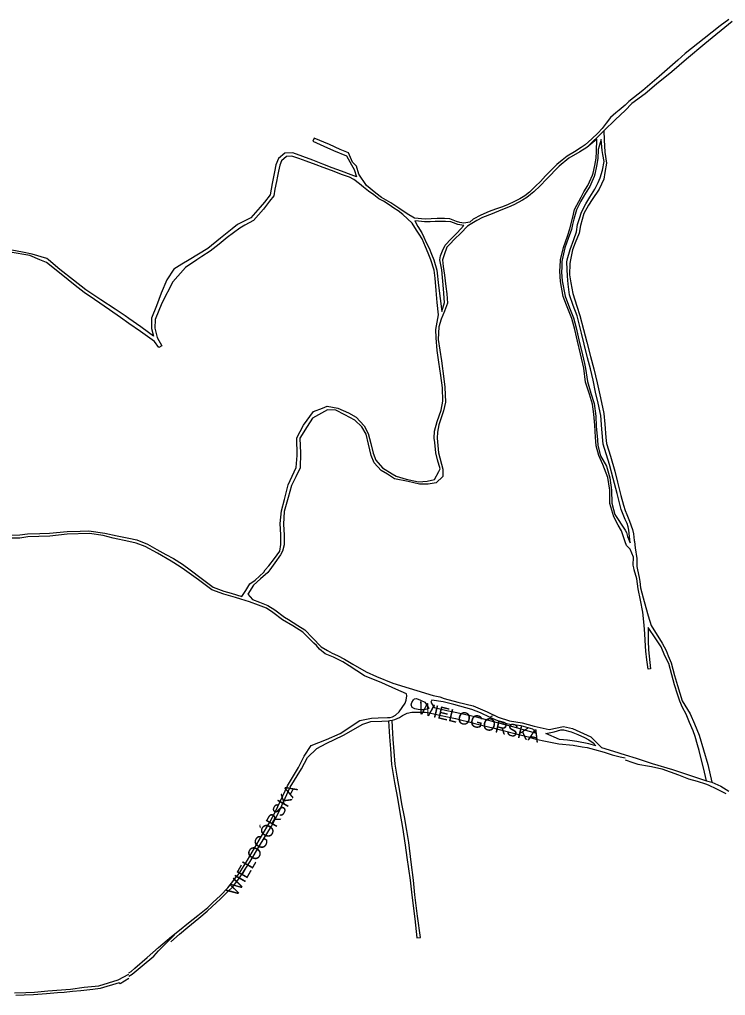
# Model space of a CAD drawing. Extents: x -304109 to -273954, y 21500 to 39796.
# Drawn here: x -301688 to -301119, y 25157 to 25944 of the extents above; entities that cross this region are included whole.
import ezdxf

# ---------------------------------------------------------------- set-up
doc = ezdxf.new("R2010")
doc.units = 0
doc.layers.add('krawedzie_ulic', color=7, linetype='Continuous')
doc.layers.add('nazwy_ulic', color=7, linetype='Continuous')

msp = doc.modelspace()

# ---------------------------------------------------------------- linework, layer by layer
at = {"layer": 'krawedzie_ulic'}
for points in [[(-301116.309, 25943.567), (-301123.262, 25938.471), (-301136.315, 25928.304), (-301151.605, 25916.218), (-301157.425, 25910.905), (-301172.587, 25897.713), (-301185.766, 25886.389), (-301196.913, 25877.455), (-301200, 25874.543), (-301204.865, 25870.477), (-301207.397, 25868.469), (-301211.799, 25864.543), (-301215.12, 25860.156), (-301218.467, 25855.732), (-301221.889, 25851.969), (-301226.826, 25847.343), (-301232.042, 25842.616), (-301235.374, 25840.52), (-301240.831, 25836.9), (-301246.581, 25833.421), (-301250.601, 25830.194)], [(-301113.534, 25942.068), (-301135.789, 25923.881), (-301150.392, 25911.718), (-301162.351, 25901.513), (-301174.705, 25891.397), (-301183.678, 25883.771), (-301194.583, 25875.803), (-301200, 25870.19), (-301207.642, 25863.035), (-301217.031, 25853.782)], [(-301217.031, 25853.782), (-301216.782, 25846.515), (-301216.406, 25836.663), (-301214.861, 25827.904), (-301216.264, 25820.282), (-301217.234, 25814.976), (-301220.926, 25806.874), (-301226.615, 25798.469), (-301229.441, 25794.044), (-301233.272, 25787.304), (-301236.025, 25777.634), (-301237.033, 25771.476), (-301240.255, 25763.665), (-301242.395, 25758.056), (-301243.976, 25750), (-301244.619, 25746.863), (-301244.717, 25737.712), (-301243.844, 25731.326), (-301242.125, 25722.714), (-301238.748, 25712.554), (-301236.447, 25705.153), (-301233.421, 25693.656), (-301230.832, 25683.571), (-301227.781, 25672.125), (-301225.269, 25661.988), (-301222.511, 25650.719), (-301219.699, 25638.624), (-301217.191, 25626.018), (-301216.35, 25617.443), (-301215.49, 25606.869), (-301214.94, 25602.06), (-301211.727, 25591.62), (-301208.152, 25579.526), (-301205.987, 25570.763), (-301203.409, 25560.079), (-301201.324, 25552.232), (-301200, 25547.845), (-301198.445, 25544.823), (-301196.379, 25539.329), (-301194.044, 25532.727), (-301193.316, 25529.192), (-301192.699, 25523.837), (-301192.393, 25522.959), (-301191.803, 25517.808), (-301190.42, 25509.363), (-301190.591, 25502.812), (-301189.921, 25500), (-301188.586, 25493.897), (-301188.14, 25490.607), (-301187.496, 25485.562), (-301185.262, 25477.485), (-301183.144, 25469.827), (-301181.271, 25463.071), (-301178.834, 25455.185), (-301170.151, 25441.09), (-301166.932, 25435.024), (-301165.109, 25430.899), (-301162.744, 25425.136), (-301160.158, 25414.975), (-301157.745, 25406.835), (-301153.916, 25394.594), (-301147.524, 25383.974), (-301144.082, 25376.079), (-301140.367, 25366.862), (-301136.82, 25355.078), (-301133.286, 25343.344), (-301130.021, 25328.915)], [(-301217.031, 25853.782), (-301230.81, 25840.552)], [(-301277.089, 25804.47), (-301280.893, 25801.484), (-301284.811, 25799.071), (-301289.618, 25796.57), (-301294.299, 25794.541), (-301298.903, 25792.765), (-301304.409, 25790.762), (-301309.636, 25788.822), (-301316.276, 25785.827), (-301322.342, 25782.666), (-301325.256, 25780.239), (-301330.037, 25779.431), (-301333.203, 25780.072), (-301335.859, 25780.89), (-301341.16, 25782.883), (-301345.61, 25783.36), (-301351.599, 25783.127), (-301361.186, 25782.809), (-301369.654, 25783.622), (-301375.577, 25786.965), (-301382.478, 25791.608), (-301388.833, 25795.944), (-301396.472, 25800.154), (-301400.945, 25803.762), (-301408.443, 25809.92), (-301414.655, 25818.927), (-301416.532, 25825.433), (-301419.633, 25828.594), (-301423.035, 25836.133), (-301429.722, 25838.917), (-301438.429, 25842.811), (-301450.772, 25847.995), (-301451.841, 25845.553), (-301442.803, 25841.633), (-301435.113, 25838.097), (-301424.563, 25833.654), (-301420.664, 25826.457), (-301418.339, 25822.814), (-301416.474, 25816.715), (-301420.91, 25818.516), (-301428.499, 25821.441), (-301436.216, 25824.188), (-301443.728, 25827.125), (-301451.724, 25830.127), (-301459.834, 25833.231), (-301467.779, 25836.17), (-301474.225, 25835.771), (-301479.403, 25831.604), (-301481.504, 25826.579), (-301482.678, 25820.764), (-301484.464, 25811.438), (-301486.25, 25802.302), (-301490.843, 25796.339), (-301494.241, 25792.245), (-301501.748, 25783.805), (-301512.457, 25778.486), (-301516.897, 25774.814), (-301526.222, 25767.471), (-301536.501, 25759.11), (-301551.573, 25750), (-301557.458, 25746.379), (-301563.92, 25742.379), (-301569.528, 25733.787), (-301573.933, 25723.06), (-301577.781, 25712.92), (-301581.832, 25702.831), (-301581.755, 25694.61), (-301580.285, 25688.39), (-301584.136, 25691.409), (-301590.307, 25695.848), (-301600, 25702.587), (-301603.048, 25704.798), (-301611.02, 25710.267), (-301622.593, 25717.817), (-301634.805, 25725.733), (-301644.751, 25733.635), (-301655.757, 25742.155), (-301664.907, 25750), (-301666.282, 25750.894), (-301678.113, 25754.592), (-301685.81, 25755.996), (-301694.308, 25757.669)], [(-301134.314, 25330.224), (-301136.646, 25340.525), (-301138.831, 25349.035), (-301140.355, 25354.495), (-301141.518, 25359.017), (-301143.417, 25365.9), (-301145.166, 25370.42), (-301148.031, 25377.211), (-301150.781, 25383.876), (-301153.64, 25389.32), (-301155.938, 25394.334), (-301157.73, 25400.035), (-301160.063, 25407.349), (-301162.157, 25415.427), (-301164.664, 25424.774), (-301167.882, 25430.814), (-301170.978, 25438.114), (-301175.279, 25444.608), (-301181.27, 25453.539), (-301181.303, 25442.925), (-301181.184, 25435.655), (-301179.378, 25420.243), (-301181.477, 25420.186), (-301182.499, 25427.504), (-301183.24, 25434.493), (-301183.512, 25438.61), (-301184.036, 25448.561), (-301184.587, 25455.626), (-301185.66, 25466.134), (-301187.595, 25475.597), (-301189.402, 25484.87), (-301190.566, 25492.773), (-301192.631, 25500), (-301192.866, 25501.808), (-301193.542, 25503.881), (-301193.219, 25510.317), (-301195.756, 25516.803), (-301198.964, 25519.742), (-301200.034, 25522.596), (-301202.733, 25531.497), (-301205.483, 25536.212), (-301209.18, 25542.757), (-301212.394, 25553.541), (-301212.365, 25564.282), (-301213.975, 25574.459), (-301217.913, 25584.91), (-301221.205, 25592.232), (-301223.265, 25600.054), (-301223.771, 25607.128), (-301224.412, 25616.659), (-301225.255, 25625.654), (-301226.209, 25633.733), (-301228.74, 25641.579), (-301231.811, 25651.434), (-301233.221, 25662.541), (-301236.031, 25674.255), (-301238.212, 25684.29), (-301240.558, 25693.715), (-301242.926, 25702.579), (-301247.133, 25713.462), (-301249.992, 25720.391), (-301252.116, 25732.501), (-301252.537, 25740.874), (-301252.068, 25749.16), (-301251.974, 25750), (-301249.59, 25759.898), (-301246.469, 25769.109), (-301244.444, 25774.782), (-301242.009, 25784.388), (-301240.67, 25790.419), (-301235.413, 25800.314), (-301233.109, 25804.638), (-301230.079, 25809.763), (-301228.641, 25812.676), (-301226.247, 25818.082), (-301225.648, 25819.799), (-301224.36, 25825.996), (-301223.199, 25831.963), (-301223.069, 25837.334), (-301222.808, 25847.121), (-301230.81, 25840.552)], [(-301246.583, 25750), (-301244.225, 25758.224), (-301241.232, 25766.39), (-301239.156, 25772.382), (-301238.377, 25778.312), (-301236.81, 25783.185), (-301235.242, 25788.312), (-301231.741, 25795.142), (-301228.407, 25800.47), (-301224.359, 25806.917), (-301221.686, 25812.17), (-301219.967, 25815.909), (-301218.31, 25822.182), (-301216.907, 25829.04), (-301217.933, 25834.845), (-301218.376, 25837.938), (-301219.21, 25846.925), (-301221.682, 25838.936), (-301221.941, 25831.643), (-301223.127, 25825.357), (-301224.301, 25819.072), (-301224.963, 25816.985), (-301227.497, 25810.829), (-301228.516, 25808.972), (-301231.774, 25803.554), (-301235.669, 25797.183), (-301239.259, 25790.252), (-301241.273, 25782.707), (-301242.242, 25778.407), (-301243.109, 25774.271), (-301245.809, 25767.122), (-301248.484, 25759.528), (-301250.652, 25750), (-301250.921, 25748.59), (-301250.995, 25744.034), (-301251.136, 25740.101), (-301250.731, 25732.963), (-301248.403, 25720.662), (-301244.671, 25711.356), (-301241.529, 25703.168), (-301239.532, 25695.232), (-301237.263, 25685.565), (-301234.286, 25673.496), (-301232.686, 25666.5), (-301231.846, 25662.417), (-301230.401, 25651.909), (-301227.496, 25642.409), (-301225.015, 25634.118), (-301223.647, 25623.915), (-301223.163, 25615.924), (-301222.339, 25604.828), (-301222.045, 25600.324), (-301219.665, 25591.88), (-301215.085, 25583.619), (-301212.333, 25574.234), (-301211.055, 25564.4), (-301210.589, 25553.774), (-301208.168, 25544.656), (-301200.039, 25532.166), (-301198.925, 25530.324), (-301198.056, 25526.953), (-301195.902, 25521.789), (-301196.93, 25531.964), (-301197.556, 25534.686), (-301198.233, 25537.51), (-301200, 25540.807), (-301203.017, 25548.881), (-301206.455, 25561.688), (-301209.648, 25573.821), (-301212.533, 25585.064), (-301217.672, 25601.277), (-301218.614, 25613.466), (-301219.578, 25624.612), (-301221.619, 25634.305), (-301223.708, 25643.233), (-301225.723, 25652.913), (-301227.8, 25662.058), (-301230.182, 25670.961), (-301232.875, 25682.013), (-301235.155, 25690.852), (-301238.506, 25704.703), (-301241.815, 25713.259), (-301244.742, 25721.6), (-301245.813, 25730.315), (-301246.456, 25736.677), (-301246.899, 25747.964), (-301246.583, 25750)], [(-301230.81, 25840.552), (-301236.457, 25837.034), (-301245.425, 25831.867), (-301253.223, 25825.386), (-301263.287, 25814.989), (-301268.516, 25809.536), (-301273.415, 25804.757), (-301276.124, 25802.496), (-301279.292, 25800.056), (-301282.726, 25797.986), (-301286.186, 25796.069), (-301289.645, 25794.305), (-301294.084, 25792.237), (-301300.023, 25790.005), (-301307.209, 25786.935), (-301314.814, 25783.992), (-301319.622, 25781.542), (-301324.875, 25778.431), (-301327.038, 25776.945), (-301332.471, 25771.378), (-301337.509, 25766.511), (-301341.389, 25762.647), (-301343.641, 25760.168), (-301345.934, 25754.062), (-301347.297, 25750), (-301346.577, 25744.467), (-301345.6, 25737.445), (-301344.465, 25728.45), (-301343.784, 25722.407), (-301343.15, 25715.078), (-301345.661, 25708.619), (-301348.312, 25702.046), (-301350.034, 25695.844), (-301350.816, 25685.673), (-301348.129, 25668.512), (-301346.162, 25654.162), (-301345.352, 25647.253), (-301344.83, 25635.279), (-301346.385, 25628.263), (-301350.165, 25616.901), (-301351.355, 25611.133), (-301351.568, 25606.157), (-301350.437, 25594.299), (-301346.986, 25581.352), (-301347.031, 25575.383), (-301352.421, 25570.355), (-301358.663, 25569.079), (-301365.698, 25569.24), (-301374.875, 25571.227), (-301385.86, 25573.401), (-301391.532, 25577.09), (-301396.706, 25580.221), (-301402.233, 25586.316), (-301404.619, 25592.38), (-301406.911, 25601.296), (-301408.794, 25609.347), (-301412.285, 25615.281), (-301417.747, 25620.752), (-301425.876, 25625.11), (-301433.101, 25628.871), (-301439.792, 25629.096), (-301451.97, 25622.333), (-301456.311, 25615.59), (-301462.132, 25606.094), (-301461.7, 25594.183), (-301461.828, 25582.296), (-301465.43, 25575.186), (-301468.83, 25568.14), (-301471.699, 25558.397), (-301474.779, 25547.037), (-301475.409, 25537.032), (-301474.935, 25528.15), (-301474.758, 25520.261), (-301476.166, 25515.166), (-301477.823, 25512.235), (-301482.369, 25505.797), (-301486.451, 25500), (-301488.014, 25498.014), (-301493.86, 25492.822), (-301499.566, 25487.858), (-301504.188, 25480.657), (-301500.404, 25476.117), (-301494.804, 25474.059), (-301488.008, 25471.365), (-301482.342, 25467.767), (-301474.55, 25462.034), (-301471.444, 25460.089), (-301463.741, 25455.284), (-301458.203, 25451.801), (-301452.077, 25445.367), (-301445.033, 25438.195), (-301439.852, 25435.068), (-301436.198, 25433.111), (-301431.743, 25431.052), (-301426.079, 25428.014)], [(-301436.637, 25821.846), (-301443.488, 25824.261), (-301449.107, 25826.433), (-301457.128, 25829.409), (-301463.103, 25831.607), (-301468.785, 25833.524), (-301472.956, 25833.288), (-301476.887, 25829.767), (-301478.44, 25826.27), (-301479.435, 25821.46), (-301480.315, 25817.223), (-301481.119, 25813.011), (-301482.28, 25806.764), (-301483.262, 25801.381), (-301486.609, 25797.237), (-301491.572, 25790.791), (-301499.524, 25781.612), (-301506.609, 25777.753), (-301510.628, 25775.493), (-301520.69, 25767.985), (-301527.382, 25762.636), (-301534.646, 25756.957), (-301541.336, 25752.588), (-301545.165, 25750), (-301554.512, 25743.853), (-301564.74, 25732.157), (-301573.615, 25714.993), (-301578.98, 25701.947), (-301579.11, 25694.782), (-301577.216, 25687.278), (-301573.468, 25680.606), (-301576.033, 25679.34), (-301579.483, 25684.18), (-301590.741, 25692.284), (-301600, 25698.617)], [(-301250.601, 25830.194), (-301255.053, 25826.623), (-301259.964, 25821.819), (-301264.023, 25817.561), (-301268.12, 25813.048), (-301272.077, 25809.274), (-301277.089, 25804.47)], [(-301406.805, 25805.323), (-301410.758, 25808.447), (-301414.202, 25811.137), (-301418.65, 25814.567), (-301422.234, 25816.634), (-301427.815, 25818.5), (-301436.637, 25821.846)], [(-301695.197, 25527.985), (-301687.947, 25528.466), (-301681.716, 25529.223), (-301671.791, 25529.387), (-301664.031, 25529.591), (-301649.838, 25531.074), (-301639.24, 25531.254), (-301632.255, 25531.479), (-301619.392, 25529.597), (-301609.569, 25527.597), (-301600.039, 25525.533), (-301593.755, 25524.185), (-301585.158, 25520.936), (-301577.538, 25516.603), (-301570.262, 25512.575), (-301564.158, 25509.281), (-301556.842, 25504.642), (-301550.594, 25500), (-301541.91, 25493.539), (-301532.08, 25486.229), (-301523.566, 25482.976), (-301517.47, 25481.262), (-301508.982, 25478.772), (-301505.82, 25483.544), (-301502.633, 25488.849), (-301498.209, 25491.802), (-301491.309, 25498.242), (-301490.217, 25500), (-301487.246, 25503.277), (-301482.749, 25509.168), (-301478.418, 25515.25), (-301477.455, 25520.483), (-301477.518, 25528.271), (-301478.107, 25537.471), (-301477.122, 25547.655), (-301474.632, 25556.697), (-301471.731, 25568.489), (-301465.11, 25582.619), (-301464.353, 25592.357), (-301464.537, 25606.419), (-301459.24, 25616.588), (-301451.071, 25627.655), (-301443.816, 25630.422), (-301440.107, 25631.997), (-301431.618, 25630.491), (-301423.007, 25626.682), (-301416.8, 25623.084), (-301410.469, 25616.1), (-301407.117, 25610.102), (-301404.916, 25601.886), (-301403.123, 25594.191), (-301400.892, 25588.444), (-301395.555, 25582.209), (-301387.755, 25577.405), (-301384.556, 25575.568), (-301376.548, 25573.247), (-301366.492, 25571.058), (-301359.497, 25571.559), (-301353.536, 25572.859), (-301350.084, 25579.371), (-301349.2, 25581.473), (-301351.093, 25588.761), (-301352.472, 25594.433), (-301353.427, 25602.69), (-301353.909, 25606.329), (-301353.634, 25611.815), (-301351.509, 25619.57), (-301348.384, 25628.843), (-301347.046, 25635.948), (-301347.283, 25646.714), (-301348.485, 25656.625), (-301350.237, 25667.489), (-301351.361, 25676.878), (-301352.309, 25687.146), (-301352.598, 25693.877), (-301350.358, 25705.655), (-301351.382, 25715.477), (-301352.278, 25725.261), (-301353.136, 25735.11), (-301353.869, 25741.649), (-301356.553, 25750), (-301358.712, 25755.174), (-301361.01, 25760.434), (-301363.561, 25766.737), (-301365.987, 25770.597), (-301368.121, 25773.846), (-301371.653, 25779.54), (-301379.264, 25786.512), (-301382.874, 25789.343), (-301386.343, 25791.689), (-301390.105, 25794.227), (-301394.871, 25797.161), (-301398.405, 25799.177), (-301402.535, 25802.377), (-301406.805, 25805.323)], [(-301599.983, 25698.605), (-301606.844, 25703.367), (-301615.699, 25709.557), (-301627.748, 25718.033), (-301636.039, 25723.539), (-301643.478, 25729.303), (-301654.64, 25738.369), (-301666.568, 25747.8), (-301671.979, 25750), (-301679.957, 25753.372), (-301695.884, 25756.119), (-301711.757, 25755.698), (-301727.289, 25757.186), (-301744.147, 25764.168), (-301765.23, 25773.201), (-301780.922, 25785.041)], [(-301349.458, 25750), (-301348.694, 25753.137), (-301347.165, 25757.055), (-301344.988, 25761.761), (-301340.128, 25766.883), (-301335.458, 25771.675), (-301329.886, 25777.484), (-301334.844, 25778.445), (-301338.429, 25779.723), (-301340.539, 25780.566), (-301344.874, 25780.928), (-301348.422, 25780.908), (-301352.974, 25780.812), (-301357.004, 25780.652), (-301361.684, 25780.493), (-301366.451, 25781.123), (-301369.49, 25781.306), (-301366.988, 25776.81), (-301363.927, 25771.562), (-301362.111, 25768.097), (-301360.245, 25763.856), (-301358.048, 25759.208), (-301356.055, 25754.547), (-301354.239, 25750), (-301351.732, 25741.667), (-301350.306, 25729.313), (-301347.797, 25708.207), (-301345.594, 25715.606), (-301346.507, 25726.549), (-301347.853, 25741.995), (-301349.458, 25750)], [(-301600.023, 25175.403), (-301598.324, 25176.428), (-301595.22, 25179.087), (-301585.213, 25187.703), (-301576.273, 25195.934), (-301565.568, 25204.719), (-301559.283, 25209.745), (-301551.96, 25215.678), (-301544.496, 25221.561), (-301536.323, 25227.943), (-301532.298, 25232.044), (-301526.194, 25237.604), (-301520.171, 25243.978), (-301515.529, 25250), (-301514.818, 25250.997), (-301511.134, 25255.387), (-301504.404, 25266.215), (-301493.092, 25285.402), (-301486.325, 25296.891), (-301481.819, 25305.48), (-301472.226, 25326.078), (-301463.389, 25340.85), (-301458.668, 25350.049), (-301453.017, 25358.498), (-301440.746, 25363.477), (-301429.722, 25368.214), (-301413.884, 25378.766), (-301404.536, 25380.665), (-301399.027, 25380.858), (-301391.624, 25381.027), (-301389.359, 25381.18), (-301387.604, 25381.664), (-301385.011, 25382.912), (-301382.202, 25385.648), (-301379.611, 25389.097), (-301377.186, 25392.774), (-301376.476, 25395.051), (-301375.959, 25398.6), (-301376.304, 25400.178), (-301384.692, 25403.977), (-301396.16, 25409.086), (-301410.085, 25414.766), (-301422.498, 25422.902), (-301427.577, 25426.118), (-301435.011, 25429.74), (-301441.744, 25432.333), (-301446.316, 25436.299), (-301448.889, 25439.122), (-301450.888, 25441.08), (-301459.842, 25449.79), (-301467.85, 25454.926), (-301476.15, 25459.921), (-301483.892, 25465.668), (-301489.023, 25469.113), (-301495.615, 25471.552), (-301502.819, 25474.233), (-301509.768, 25476.584), (-301514.158, 25477.765), (-301523.525, 25480.61), (-301533.197, 25483.926), (-301543.969, 25492.088), (-301555.135, 25500), (-301558.616, 25502.486), (-301565.869, 25507.19), (-301577.095, 25513.435), (-301586.818, 25518.82), (-301594.243, 25521.715), (-301600, 25523.052), (-301612.714, 25525.724), (-301620.819, 25527.681), (-301631.924, 25529.344), (-301649.838, 25528.822), (-301663.878, 25527.378), (-301681.663, 25526.704), (-301687.956, 25525.782), (-301695.781, 25525.578)], [(-301426.079, 25428.014), (-301419.37, 25424.099), (-301408.612, 25417.845), (-301400.339, 25414.262), (-301387.179, 25408.925), (-301374.045, 25404.872), (-301368.013, 25402.903)], [(-301368.013, 25402.903), (-301354.6, 25398.775), (-301349.243, 25397.836), (-301345.73, 25396.463), (-301334.735, 25393.581), (-301322.404, 25390.418), (-301311.242, 25385.691), (-301302.395, 25381.446), (-301293.181, 25378.486), (-301283.078, 25376.964), (-301273.407, 25374.093), (-301261.293, 25371.529), (-301249.655, 25373.887), (-301242.466, 25372.402), (-301227.624, 25365.615), (-301219.014, 25356.867), (-301209.419, 25353.933), (-301200, 25351.113), (-301190.99, 25348.434), (-301178.187, 25344.151), (-301161.78, 25339.116), (-301148.799, 25334.985), (-301134.314, 25330.224)], [(-301358.175, 25388.444), (-301359.701, 25387.782), (-301361.952, 25387.349), (-301363.834, 25387.297), (-301366.799, 25387.652), (-301369.433, 25388.223), (-301371.61, 25389.24), (-301372.413, 25391.237), (-301371.831, 25393.12), (-301370.485, 25395.461), (-301369.672, 25396.262), (-301368.273, 25396.505), (-301365.027, 25395.005), (-301361.45, 25393.404), (-301359.819, 25391.128), (-301358.175, 25388.444)], [(-301271.504, 25368.446), (-301274.422, 25371.854), (-301283.89, 25374.547), (-301287.796, 25374.978), (-301292.999, 25375.472), (-301297.682, 25376.665), (-301302.684, 25378.38), (-301308.87, 25381.125), (-301316.685, 25384.773), (-301323.507, 25387.632), (-301338.053, 25391.569), (-301346.693, 25393.754), (-301355.88, 25395.225), (-301356.489, 25393.368), (-301353.838, 25389.273), (-301343.708, 25386.72), (-301337.028, 25385.413), (-301327.166, 25383.293), (-301319.989, 25381.719), (-301311.056, 25379.394), (-301303.115, 25377.146), (-301295.747, 25375.203), (-301287.832, 25372.993), (-301280.323, 25370.808), (-301271.504, 25368.446)], [(-301566.361, 25200.451), (-301559.23, 25206.638), (-301552.617, 25212.213), (-301543.748, 25219.463), (-301536.907, 25225.051), (-301532.969, 25228.782), (-301526.371, 25234.841), (-301520.168, 25240.91), (-301516.383, 25244.552), (-301512.247, 25250), (-301509.364, 25254.255), (-301502.176, 25265.211), (-301494.686, 25277.833), (-301485.189, 25293.559), (-301479.35, 25304.399), (-301469.897, 25324.985), (-301460.806, 25339.834), (-301456.008, 25348.956), (-301448.549, 25356.287), (-301441.086, 25360.182), (-301426.986, 25366.917), (-301411.438, 25375.905), (-301404.876, 25377.879), (-301396.035, 25378.15), (-301390.647, 25378.568)], [(-301390.647, 25378.568), (-301389.763, 25378.636), (-301387.846, 25379.053)], [(-301390.647, 25378.568), (-301389.824, 25365.648), (-301389.215, 25355.905), (-301388.347, 25343.21), (-301385.837, 25328.646), (-301383.557, 25316.016), (-301381.674, 25304.644), (-301379.573, 25292.383), (-301377.304, 25278.175), (-301375.97, 25268.419), (-301373.302, 25250), (-301371.948, 25238.026), (-301369.59, 25219.002), (-301367.886, 25203.641), (-301364.936, 25203.855), (-301367.272, 25221.111), (-301369.367, 25238.341), (-301370.694, 25250), (-301372.416, 25264.515), (-301374.355, 25280.3), (-301376.021, 25290.018), (-301377.891, 25301.161), (-301379.901, 25311.654), (-301381.656, 25321.703), (-301383.718, 25333.888), (-301385.473, 25343.44), (-301386.235, 25353.693), (-301386.896, 25363.614), (-301387.531, 25373.345), (-301387.846, 25379.053)], [(-301387.846, 25379.053), (-301385.719, 25379.515), (-301381.994, 25381.209), (-301379.349, 25382.711), (-301375.764, 25384.557), (-301371.885, 25385.309), (-301369.112, 25385.527), (-301364.456, 25385.49), (-301361.135, 25385.339), (-301357.916, 25384.794), (-301352.89, 25383.778), (-301348.156, 25382.699), (-301343.206, 25381.709), (-301336.615, 25380.401), (-301332.555, 25379.22), (-301325.824, 25377.633), (-301321.077, 25376.236), (-301314.791, 25374.635), (-301306.659, 25372.705), (-301299.406, 25370.851), (-301287.876, 25367.918), (-301278.052, 25365.441), (-301272.02, 25363.701), (-301264.131, 25362.127), (-301257.438, 25360.744), (-301253.341, 25359.88), (-301241.801, 25358.817), (-301234.624, 25357.599), (-301230.451, 25357.015), (-301224.699, 25355.44), (-301216.974, 25353.23), (-301210.306, 25351.007), (-301203.981, 25349.509), (-301200, 25348.645)], [(-301223.456, 25358.341), (-301229.259, 25360.043), (-301238.929, 25361.769), (-301246.386, 25362.987), (-301252.912, 25363.328), (-301263.769, 25368.221), (-301257.181, 25369.712), (-301251.84, 25371.177), (-301249.69, 25371.19), (-301243.353, 25369.717), (-301238.173, 25367.544), (-301232.572, 25364.99), (-301229.224, 25363.236), (-301225.659, 25360.63), (-301223.456, 25358.341)], [(-301200, 25347.06), (-301193.826, 25344.879), (-301189.774, 25343.57), (-301180.201, 25342.047), (-301178.774, 25341.531), (-301170.471, 25339.712), (-301163.554, 25337.394), (-301156.954, 25335.012), (-301148.875, 25331.833), (-301141.97, 25329.744), (-301135.168, 25327.667), (-301132.964, 25326.987), (-301126.233, 25323.639), (-301118.623, 25320.014)], [(-301134.314, 25330.224), (-301130.021, 25328.915)], [(-301130.021, 25328.915), (-301122.705, 25325.772), (-301116.404, 25321.876)], [(-301600, 25172.666), (-301597.283, 25174.242), (-301589.213, 25181.018), (-301580.029, 25188.829), (-301576.119, 25192.994), (-301563.272, 25206)], [(-301692.299, 25159.236), (-301683.226, 25159.587), (-301676.084, 25159.792), (-301665.483, 25160.773), (-301647.053, 25162.262), (-301636.171, 25163.75), (-301624.273, 25164.98), (-301608.829, 25169.729), (-301600, 25174.348)], [(-301600, 25170.818), (-301607.113, 25166.549), (-301607.949, 25167.339), (-301623.239, 25162.793), (-301629.011, 25161.923), (-301638.774, 25160.812), (-301645.612, 25160.327), (-301652.12, 25159.637), (-301657.738, 25159.173), (-301666.61, 25158.466), (-301677.032, 25157.586), (-301684.556, 25157.306), (-301691.265, 25157.15)]]:
    msp.add_lwpolyline(points, dxfattribs=at)

# ---------------------------------------------------------------- texts
at = {"layer": 'nazwy_ulic'}
for rotation, p in [(346.379483, (-301367.65, 25384.478)), (60.316953, (-301513.207, 25236.399))]:
    msp.add_text('WIELOGÓRSKA', height=10, rotation=rotation, dxfattribs=at).set_placement(p)

doc.saveas('drawing.dxf')
